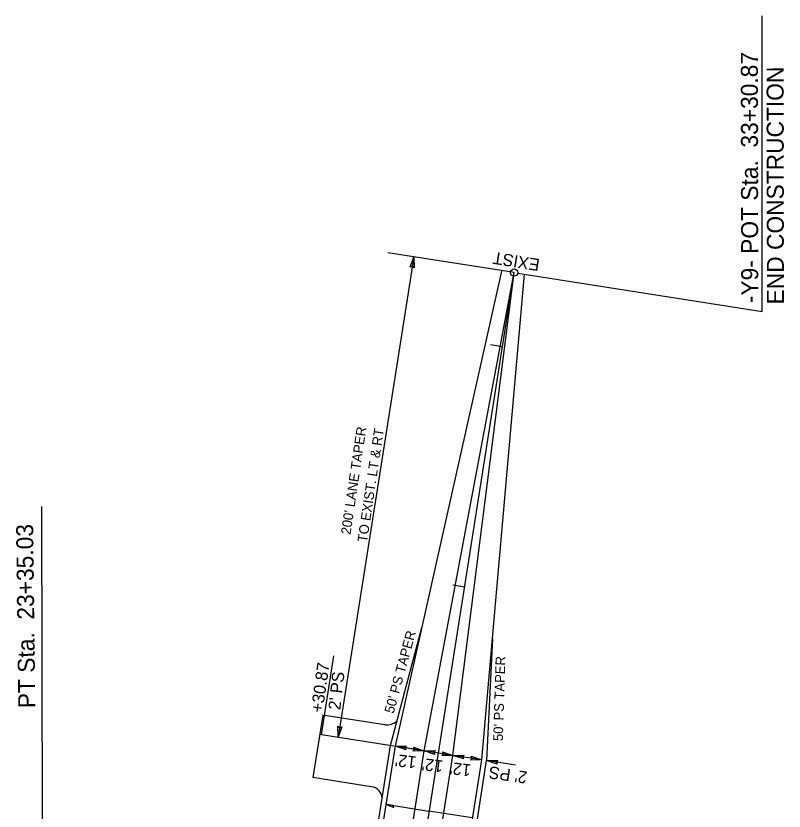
# Model space of a CAD drawing. Extents: x 2389099 to 2405615, y 552200 to 573532.
# Drawn here: x 2397666 to 2397981.9, y 554646.7 to 554973.7 of the extents above; entities that cross this region are included whole.
import ezdxf

# ---------------------------------------------------------------- set-up
doc = ezdxf.new("R2010")
doc.units = 0
for name, color, linetype in [('Prop Dimension', 7, 'Continuous'), ('Prop Dimension Text', 7, 'Continuous'), ('Prop EOT', 7, 'Continuous'), ('Prop Horizontal Alignment', 7, 'Continuous'), ('Prop Horizontal Alignment Curve and Spiral Data', 7, 'Continuous'), ('Prop Horizontal Alignment Station Label', 7, 'Continuous'), ('Prop Horizontal Alignment Tick Small', 7, 'Continuous'), ('Prop Lane Lines', 7, 'Continuous'), ('Prop Superelevation  Arrow CELL', 7, 'Continuous')]:
    doc.layers.add(name, color=color, linetype=linetype)

msp = doc.modelspace()

# ---------------------------------------------------------------- linework, layer by layer
at = {"layer": 'Prop Dimension'}
for p, q in [((2397829.64, 554874.6), (2397798.55, 554677.03)), ((2397870.89, 554868.11), (2397818.87, 554876.3)), ((2397791.69, 554678.11), (2397796.79, 554710.5)), ((2397839.8, 554670.54), (2397791.69, 554678.11)), ((2397833.87, 554671.47), (2397822.02, 554673.34)), ((2397845.73, 554669.61), (2397833.87, 554671.47)), ((2397857.58, 554667.74), (2397845.73, 554669.61)), ((2397871.41, 554665.56), (2397859.56, 554667.43))]:
    msp.add_line(p, q, dxfattribs=at)
for points in [[(2397828.17, 554870.28), (2397829.64, 554874.6), (2397829.72, 554870.01), (2397829.02, 554870.7)], [(2397799.98, 554681.37), (2397798.55, 554677.03), (2397798.43, 554681.63), (2397799.14, 554680.94)], [(2397826.34, 554671.87), (2397822.02, 554673.34), (2397826.61, 554673.43), (2397825.92, 554672.72)], [(2397829.55, 554672.94), (2397833.87, 554671.47), (2397829.28, 554671.39), (2397829.97, 554672.09)], [(2397838.2, 554670.01), (2397833.87, 554671.47), (2397838.47, 554671.56), (2397837.77, 554670.86)], [(2397841.4, 554671.07), (2397845.73, 554669.61), (2397841.13, 554669.52), (2397841.82, 554670.22)], [(2397850.05, 554668.14), (2397845.73, 554669.61), (2397850.32, 554669.69), (2397849.63, 554668.99)], [(2397853.26, 554669.21), (2397857.58, 554667.74), (2397852.99, 554667.65), (2397853.68, 554668.36)], [(2397863.88, 554665.97), (2397859.56, 554667.43), (2397864.15, 554667.52), (2397863.46, 554666.82)]]:
    msp.add_lwpolyline(points, close=True, dxfattribs=at)
at = {"layer": 'Prop EOT'}
for p, q in [((2397822.02, 554673.34), (2397865.83, 554868.75)), ((2397857.58, 554667.74), (2397875.17, 554867.44)), ((2397820.04, 554673.65), (2397832.98, 554722.23)), ((2397861.98, 554717.66), (2397859.56, 554667.43)), ((2397792.15, 554686.17), (2397788.04, 554660.52)), ((2397817.68, 554682.12), (2397792.11, 554686.14)), ((2397812.38, 554624.96), (2397820.04, 554673.65)), ((2397814.35, 554624.65), (2397822.02, 554673.34)), ((2397847.45, 554603.39), (2397857.58, 554667.74)), ((2397848.07, 554594.47), (2397859.56, 554667.43)), ((2397812.95, 554656.54), (2397788.03, 554660.47))]:
    msp.add_line(p, q, dxfattribs=at)
for centre, radius, start, end in [((2397818.09, 554689.37), 7.26, 266.8298, 309.8923), ((2397811.8, 554651.85), 4.83, 1.4727, 85.9139)]:
    msp.add_arc(centre, radius, start, end, dxfattribs=at)
at = {"layer": 'Prop Horizontal Alignment'}
for p, q in [((2397839.8, 554670.54), (2397870.89, 554868.11)), ((2397778.01, 554277.92), (2397839.8, 554670.54))]:
    msp.add_line(p, q, dxfattribs=at)
at = {"layer": 'Prop Horizontal Alignment Curve and Spiral Data'}
for p, q in [((2397972.89, 554852.06), (2397972.88, 554973.66)), ((2397872.38, 554867.87), (2397972.89, 554852.06))]:
    msp.add_line(p, q, dxfattribs=at)
msp.add_circle((2397870.89, 554868.11), 1.5, dxfattribs=at)
at = {"layer": 'Prop Horizontal Alignment Station Label'}
msp.add_line((2397676.9, 554642.99), (2397676.63, 554771.92), dxfattribs=at)
at = {"layer": 'Prop Horizontal Alignment Tick Small'}
for p, q in [((2397866.08, 554837.61), (2397861.14, 554838.39)), ((2397850.54, 554738.83), (2397845.6, 554739.61))]:
    msp.add_line(p, q, dxfattribs=at)
at = {"layer": 'Prop Lane Lines'}
for p, q in [((2397833.87, 554671.47), (2397870.89, 554868.11)), ((2397845.73, 554669.61), (2397870.89, 554868.11)), ((2397772.08, 554278.86), (2397833.87, 554671.47)), ((2397783.93, 554276.99), (2397845.73, 554669.61))]:
    msp.add_line(p, q, dxfattribs=at)
at = {"layer": 'Prop Superelevation  Arrow CELL'}
for p in [(2397818.02, 554649.49), (2397853.58, 554643.89)]:
    msp.add_line(p, (2397835.8, 554646.69), dxfattribs=at)
msp.add_lwpolyline([(2397818.02, 554649.49), (2397821.35, 554648.16), (2397820.93, 554649.03)], close=True, dxfattribs=at)

# ---------------------------------------------------------------- texts
at = {"layer": 'Prop Dimension Text'}
for s, height, rotation, p in [('EXIST', 5, 170.7877, (2397881.69, 554873.63)), ("200' LANE TAPER", 4, 81.4977, (2397803.55, 554760.2)), ('TO EXIST. LT & RT', 4, 81.4977, (2397810.36, 554757.01)), ("50' PS TAPER", 4, 74.6916, (2397821.3, 554686.58)), ('+30.87', 5, 82.1194, (2397792.14, 554686.97)), ("50' PS TAPER", 4, 88.2743, (2397866.23, 554675.45)), ("2' PS", 5, 83.5276, (2397799.37, 554688.08)), ("12'", 5, 173.2607, (2397830.91, 554669.11)), ("12'", 5, 173.2607, (2397841.92, 554667.47)), ("12'", 5, 173.2607, (2397853.39, 554665.84)), ("2' PS", 5, 171.6357, (2397876.51, 554662.88))]:
    msp.add_text(s, height=height, rotation=rotation, dxfattribs=at).set_placement(p)
at = {"layer": 'Prop Horizontal Alignment Curve and Spiral Data'}
for s, p in [('-Y9- POT Sta.  33+30.87', (2397971.28, 554855.55)), ('END CONSTRUCTION', (2397981.85, 554855.04))]:
    msp.add_text(s, height=7, rotation=90.093, dxfattribs=at).set_placement(p)
at = {"layer": 'Prop Horizontal Alignment Station Label'}
msp.add_text('PT Sta.  23+35.03', height=7, rotation=90.6849, dxfattribs=at).set_placement((2397673.95, 554689.05))

doc.saveas('drawing.dxf')
